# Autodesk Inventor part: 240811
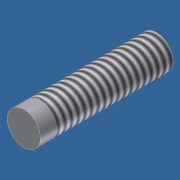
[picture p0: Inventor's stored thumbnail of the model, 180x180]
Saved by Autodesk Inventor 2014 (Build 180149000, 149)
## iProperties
Shininess: 20.0
Length Units: 11272
Angle Units: 11279
Time Units: 11290
Mass Units: 11286
Length Display Precision: 3
Angle Display Precision: 2
Company: Autodesk, Inc.
Created: 2002-07
Part Number: 240811
Material: Stainless Steel
Description: STUD, WELD; 3/8" NC x 1" (SS)
Document SubType Name: Modeling
Designer: Autodesk, Inc.
Density: 7.75 g/cm^3
Mass: 15.78 g
Surface Area: 9.9758 cm^2
Volume: 2.03613 cm^3
Appearance: Stainless Steel
Density: 0.0
Volumn: 0.0
Area: 0.0
PropertySet Name: Model Information
Control State: 0
Master: False
Checked Out: True
Last Check In By: JT
Last Check In Date: 2003-06-20
Title: STUD, WELD; 3/8" NC x 1" (SS)
Author: Autodesk, Inc.
Comments: Pre-welded Length = 1.125" Post-weld Length = 1.0"
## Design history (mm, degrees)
derived "Threaded Weld Stud.ipt"
body "Solid1"
tag "TaggingFeature2"
feature "Solid1::Threaded Weld Stud.ipt" dims "ScaleForDerivedMember" = 10
